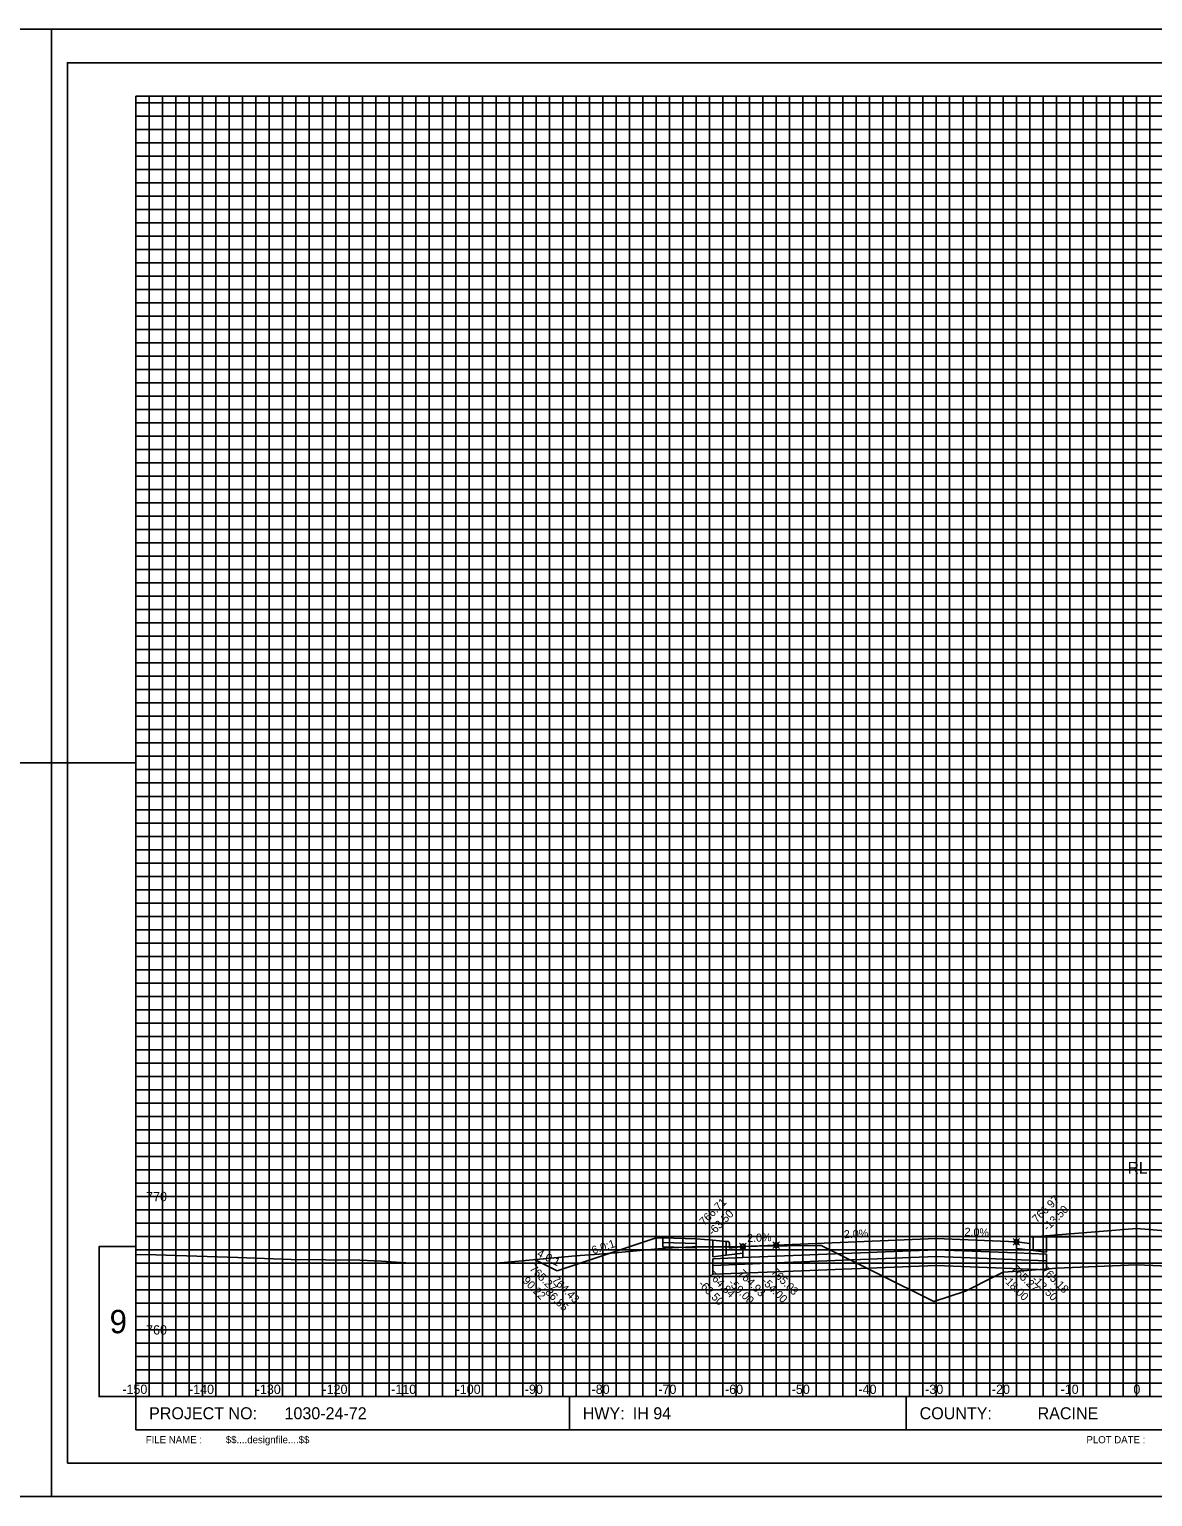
# Model space of a CAD drawing. Extents: x 578243 to 601557, y 174899 to 175559.
# Drawn here: x 601213.9 to 601382.3, y 174898.8 to 175118.8 of the extents above; entities that cross this region are included whole.
import ezdxf

# ---------------------------------------------------------------- set-up
doc = ezdxf.new("R2010")
doc.units = 0
for name, color, linetype in [('E_PROF_Grid', 7, 'Continuous'), ('E_PROF_GridMin', 7, 'Continuous'), ('P_CRDR_Label', 7, 'Continuous'), ('P_CRDR_Link', 7, 'Continuous'), ('P_E_XS_Ground', 7, 'Continuous'), ('P_XS_Text', 7, 'Continuous'), ('PLT_Sheet_Border', 7, 'Continuous'), ('PLT_Sheet_Info', 7, 'Continuous')]:
    doc.layers.add(name, color=color, linetype=linetype)

msp = doc.modelspace()

# ---------------------------------------------------------------- linework, layer by layer
at = {"layer": 'E_PROF_Grid'}
for p, q in [((601239.84, 174913.8), (601239.84, 175108.8)), ((601249.84, 174913.8), (601249.84, 175108.8)), ((601259.84, 174913.8), (601259.84, 175108.8)), ((601269.84, 174913.8), (601269.84, 175108.8)), ((601279.84, 174913.8), (601279.84, 175108.8)), ((601289.84, 174913.8), (601289.84, 175108.8)), ((601299.84, 174913.8), (601299.84, 175108.8)), ((601309.84, 174913.8), (601309.84, 175108.8)), ((601319.84, 174913.8), (601319.84, 175108.8)), ((601329.84, 174913.8), (601329.84, 175108.8)), ((601339.84, 174913.8), (601339.84, 175108.8)), ((601349.84, 174913.8), (601349.84, 175108.8)), ((601359.84, 174913.8), (601359.84, 175108.8)), ((601369.84, 174913.8), (601369.84, 175108.8)), ((601379.84, 174913.8), (601379.84, 175108.8)), ((601229.84, 175103.8), (601544.84, 175103.8)), ((601229.84, 175093.8), (601544.84, 175093.8)), ((601229.84, 175083.8), (601544.84, 175083.8)), ((601229.84, 175073.8), (601544.84, 175073.8)), ((601229.84, 175063.8), (601544.84, 175063.8)), ((601229.84, 175053.8), (601544.84, 175053.8)), ((601229.84, 175043.8), (601544.84, 175043.8)), ((601229.84, 175033.8), (601544.84, 175033.8)), ((601229.84, 175023.8), (601544.84, 175023.8)), ((601229.84, 175013.8), (601544.84, 175013.8)), ((601229.84, 175003.8), (601544.84, 175003.8)), ((601229.84, 174993.8), (601544.84, 174993.8)), ((601229.84, 174983.8), (601544.84, 174983.8)), ((601229.84, 174973.8), (601544.84, 174973.8)), ((601229.84, 174963.8), (601544.84, 174963.8)), ((601229.84, 174953.8), (601544.84, 174953.8)), ((601229.84, 174943.8), (601544.84, 174943.8)), ((601229.84, 174933.8), (601544.84, 174933.8)), ((601229.84, 174923.8), (601544.84, 174923.8))]:
    msp.add_line(p, q, dxfattribs=at)
at = {"layer": 'E_PROF_GridMin'}
for p, q in [((601229.84, 175107.8), (601544.84, 175107.8)), ((601231.84, 174913.8), (601231.84, 175108.8)), ((601233.84, 174913.8), (601233.84, 175108.8)), ((601235.84, 174913.8), (601235.84, 175108.8)), ((601237.84, 174913.8), (601237.84, 175108.8)), ((601241.84, 174913.8), (601241.84, 175108.8)), ((601243.84, 174913.8), (601243.84, 175108.8)), ((601245.84, 174913.8), (601245.84, 175108.8)), ((601247.84, 174913.8), (601247.84, 175108.8)), ((601251.84, 174913.8), (601251.84, 175108.8)), ((601253.84, 174913.8), (601253.84, 175108.8)), ((601255.84, 174913.8), (601255.84, 175108.8)), ((601257.84, 174913.8), (601257.84, 175108.8)), ((601261.84, 174913.8), (601261.84, 175108.8)), ((601263.84, 174913.8), (601263.84, 175108.8)), ((601265.84, 174913.8), (601265.84, 175108.8)), ((601267.84, 174913.8), (601267.84, 175108.8)), ((601271.84, 174913.8), (601271.84, 175108.8)), ((601273.84, 174913.8), (601273.84, 175108.8)), ((601275.84, 174913.8), (601275.84, 175108.8)), ((601277.84, 174913.8), (601277.84, 175108.8)), ((601281.84, 174913.8), (601281.84, 175108.8)), ((601283.84, 174913.8), (601283.84, 175108.8)), ((601285.84, 174913.8), (601285.84, 175108.8)), ((601287.84, 174913.8), (601287.84, 175108.8)), ((601291.84, 174913.8), (601291.84, 175108.8)), ((601293.84, 174913.8), (601293.84, 175108.8)), ((601295.84, 174913.8), (601295.84, 175108.8)), ((601297.84, 174913.8), (601297.84, 175108.8)), ((601301.84, 174913.8), (601301.84, 175108.8)), ((601303.84, 174913.8), (601303.84, 175108.8)), ((601305.84, 174913.8), (601305.84, 175108.8)), ((601307.84, 174913.8), (601307.84, 175108.8)), ((601311.84, 174913.8), (601311.84, 175108.8)), ((601313.84, 174913.8), (601313.84, 175108.8)), ((601315.84, 174913.8), (601315.84, 175108.8)), ((601317.84, 174913.8), (601317.84, 175108.8)), ((601321.84, 174913.8), (601321.84, 175108.8)), ((601323.84, 174913.8), (601323.84, 175108.8)), ((601325.84, 174913.8), (601325.84, 175108.8)), ((601327.84, 174913.8), (601327.84, 175108.8)), ((601331.84, 174913.8), (601331.84, 175108.8)), ((601333.84, 174913.8), (601333.84, 175108.8)), ((601335.84, 174913.8), (601335.84, 175108.8)), ((601337.84, 174913.8), (601337.84, 175108.8)), ((601341.84, 174913.8), (601341.84, 175108.8)), ((601343.84, 174913.8), (601343.84, 175108.8)), ((601345.84, 174913.8), (601345.84, 175108.8)), ((601347.84, 174913.8), (601347.84, 175108.8)), ((601351.84, 174913.8), (601351.84, 175108.8)), ((601353.84, 174913.8), (601353.84, 175108.8)), ((601355.84, 174913.8), (601355.84, 175108.8)), ((601357.84, 174913.8), (601357.84, 175108.8)), ((601361.84, 174913.8), (601361.84, 175108.8)), ((601363.84, 174913.8), (601363.84, 175108.8)), ((601365.84, 174913.8), (601365.84, 175108.8)), ((601367.84, 174913.8), (601367.84, 175108.8)), ((601371.84, 174913.8), (601371.84, 175108.8)), ((601373.84, 174913.8), (601373.84, 175108.8)), ((601375.84, 174913.8), (601375.84, 175108.8)), ((601377.84, 174913.8), (601377.84, 175108.8)), ((601381.84, 174913.8), (601381.84, 175108.8)), ((601229.84, 175105.8), (601544.84, 175105.8)), ((601229.84, 175101.8), (601544.84, 175101.8)), ((601229.84, 175099.8), (601544.84, 175099.8)), ((601229.84, 175097.8), (601544.84, 175097.8)), ((601229.84, 175095.8), (601544.84, 175095.8)), ((601229.84, 175091.8), (601544.84, 175091.8)), ((601229.84, 175089.8), (601544.84, 175089.8)), ((601229.84, 175087.8), (601544.84, 175087.8)), ((601229.84, 175085.8), (601544.84, 175085.8)), ((601229.84, 175081.8), (601544.84, 175081.8)), ((601229.84, 175079.8), (601544.84, 175079.8)), ((601229.84, 175077.8), (601544.84, 175077.8)), ((601229.84, 175075.8), (601544.84, 175075.8)), ((601229.84, 175071.8), (601544.84, 175071.8)), ((601229.84, 175069.8), (601544.84, 175069.8)), ((601229.84, 175067.8), (601544.84, 175067.8)), ((601229.84, 175065.8), (601544.84, 175065.8)), ((601229.84, 175061.8), (601544.84, 175061.8)), ((601229.84, 175059.8), (601544.84, 175059.8)), ((601229.84, 175057.8), (601544.84, 175057.8)), ((601229.84, 175055.8), (601544.84, 175055.8)), ((601229.84, 175051.8), (601544.84, 175051.8)), ((601229.84, 175049.8), (601544.84, 175049.8)), ((601229.84, 175047.8), (601544.84, 175047.8)), ((601229.84, 175045.8), (601544.84, 175045.8)), ((601229.84, 175041.8), (601544.84, 175041.8)), ((601229.84, 175039.8), (601544.84, 175039.8)), ((601229.84, 175037.8), (601544.84, 175037.8)), ((601229.84, 175035.8), (601544.84, 175035.8)), ((601229.84, 175031.8), (601544.84, 175031.8)), ((601229.84, 175029.8), (601544.84, 175029.8)), ((601229.84, 175027.8), (601544.84, 175027.8)), ((601229.84, 175025.8), (601544.84, 175025.8)), ((601229.84, 175021.8), (601544.84, 175021.8)), ((601229.84, 175019.8), (601544.84, 175019.8)), ((601229.84, 175017.8), (601544.84, 175017.8)), ((601229.84, 175015.8), (601544.84, 175015.8)), ((601229.84, 175011.8), (601544.84, 175011.8)), ((601229.84, 175009.8), (601544.84, 175009.8)), ((601229.84, 175007.8), (601544.84, 175007.8)), ((601229.84, 175005.8), (601544.84, 175005.8)), ((601229.84, 175001.8), (601544.84, 175001.8)), ((601229.84, 174999.8), (601544.84, 174999.8)), ((601229.84, 174997.8), (601544.84, 174997.8)), ((601229.84, 174995.8), (601544.84, 174995.8)), ((601229.84, 174991.8), (601544.84, 174991.8)), ((601229.84, 174989.8), (601544.84, 174989.8)), ((601229.84, 174987.8), (601544.84, 174987.8)), ((601229.84, 174985.8), (601544.84, 174985.8)), ((601229.84, 174981.8), (601544.84, 174981.8)), ((601229.84, 174979.8), (601544.84, 174979.8)), ((601229.84, 174977.8), (601544.84, 174977.8)), ((601229.84, 174975.8), (601544.84, 174975.8)), ((601229.84, 174971.8), (601544.84, 174971.8)), ((601229.84, 174969.8), (601544.84, 174969.8)), ((601229.84, 174967.8), (601544.84, 174967.8)), ((601229.84, 174965.8), (601544.84, 174965.8)), ((601229.84, 174961.8), (601544.84, 174961.8)), ((601229.84, 174959.8), (601544.84, 174959.8)), ((601229.84, 174957.8), (601544.84, 174957.8)), ((601229.84, 174955.8), (601544.84, 174955.8)), ((601229.84, 174951.8), (601544.84, 174951.8)), ((601229.84, 174949.8), (601544.84, 174949.8)), ((601229.84, 174947.8), (601544.84, 174947.8)), ((601229.84, 174945.8), (601544.84, 174945.8)), ((601229.84, 174941.8), (601544.84, 174941.8)), ((601229.84, 174939.8), (601544.84, 174939.8)), ((601229.84, 174937.8), (601544.84, 174937.8)), ((601229.84, 174935.8), (601544.84, 174935.8)), ((601229.84, 174931.8), (601544.84, 174931.8)), ((601229.84, 174929.8), (601544.84, 174929.8)), ((601229.84, 174927.8), (601544.84, 174927.8)), ((601229.84, 174925.8), (601544.84, 174925.8)), ((601229.84, 174921.8), (601544.84, 174921.8)), ((601229.84, 174919.8), (601544.84, 174919.8)), ((601229.84, 174917.8), (601544.84, 174917.8)), ((601229.84, 174915.8), (601544.84, 174915.8)), ((601217.19, 174898.8), (601217.19, 174908.8)), ((601207.19, 174898.8), (601217.19, 174898.8))]:
    msp.add_line(p, q, dxfattribs=at)
at = {"layer": 'P_CRDR_Label'}
for points in [[(601379.84, 174946.61), (601379.84, 174938.99)], [(601361.34, 174936.5), (601362.33, 174937.49)], [(601361.34, 174937.49), (601362.33, 174936.5)], [(601320.34, 174935.82), (601321.33, 174936.81)], [(601320.34, 174936.81), (601321.33, 174935.82)], [(601325.34, 174936.02), (601326.33, 174937.01)], [(601325.34, 174937.01), (601326.33, 174936.02)]]:
    msp.add_lwpolyline(points, dxfattribs=at)
for centre in [(601320.84, 174936.32), (601325.84, 174936.52), (601361.84, 174937)]:
    msp.add_circle(centre, 0.35, dxfattribs=at)
at = {"layer": 'P_CRDR_Link'}
for points in [[(601307.84, 174937.61), (601292.99, 174932.66)], [(601307.84, 174937.61), (601292.99, 174932.66)], [(601308.84, 174937.58), (601307.84, 174937.61)], [(601308.84, 174937.58), (601307.84, 174937.61)], [(601313.84, 174937.43), (601308.84, 174937.58)], [(601313.84, 174937.43), (601308.84, 174937.58)], [(601308.84, 174937.58), (601308.84, 174936.91)], [(601313.84, 174937.43), (601313.83, 174936.76)], [(601316.34, 174937.23), (601313.84, 174937.43)], [(601316.34, 174937.23), (601313.84, 174937.43)], [(601349.84, 174937.48), (601325.84, 174936.52)], [(601361.84, 174937), (601349.84, 174937.48)], [(601349.84, 174937.48), (601349.84, 174935.81)], [(601349.84, 174937.48), (601349.84, 174935.81)], [(601363.84, 174936.75), (601363.85, 174937.43)], [(601363.84, 174936.75), (601363.85, 174937.43)], [(601363.85, 174937.43), (601363.88, 174937.59)], [(601363.85, 174937.43), (601363.88, 174937.59)], [(601363.88, 174937.59), (601363.94, 174937.7)], [(601363.88, 174937.59), (601363.94, 174937.7)], [(601363.94, 174937.7), (601364.02, 174937.75)], [(601363.94, 174937.7), (601364.02, 174937.75)], [(601364.02, 174937.75), (601364.34, 174937.75)], [(601364.02, 174937.75), (601364.34, 174937.75)], [(601364.34, 174937.75), (601379.84, 174938.99)], [(601364.34, 174937.75), (601379.84, 174938.99)], [(601364.34, 174937.75), (601364.34, 174935.68)], [(601364.34, 174937.75), (601366.34, 174937.73)], [(601364.34, 174935.68), (601364.34, 174937.75)], [(601366.34, 174937.73), (601366.34, 174935.43)], [(601366.34, 174937.73), (601366.34, 174935.43)], [(601366.34, 174937.73), (601366.34, 174935.43)], [(601366.34, 174937.73), (601369.84, 174937.7)], [(601366.34, 174937.73), (601369.84, 174937.7)], [(601395.34, 174937.75), (601379.84, 174938.99)], [(601395.34, 174937.75), (601379.84, 174938.99)], [(601313.83, 174936.76), (601308.84, 174936.91)], [(601308.85, 174936.25), (601308.84, 174936.91)], [(601313.83, 174936.1), (601308.85, 174936.25)], [(601313.83, 174936.76), (601313.83, 174936.1)], [(601318.34, 174937.07), (601316.34, 174937.23)], [(601316.34, 174937.23), (601316.34, 174934.75)], [(601316.34, 174937.23), (601316.34, 174934.75)], [(601316.34, 174937.23), (601316.34, 174934.75)], [(601318.66, 174937.07), (601318.34, 174937.07)], [(601318.66, 174937.07), (601318.34, 174937.07)], [(601318.34, 174937.07), (601318.34, 174935)], [(601318.34, 174935), (601318.34, 174937.07)], [(601318.34, 174935), (601320.84, 174935.32)], [(601318.34, 174935), (601320.84, 174935.32)], [(601318.74, 174937.02), (601318.66, 174937.07)], [(601318.74, 174937.02), (601318.66, 174937.07)], [(601318.8, 174936.91), (601318.74, 174937.02)], [(601318.8, 174936.91), (601318.74, 174937.02)], [(601318.82, 174936.75), (601318.8, 174936.91)], [(601318.82, 174936.75), (601318.8, 174936.91)], [(601318.84, 174936.07), (601318.82, 174936.75)], [(601318.84, 174936.07), (601318.82, 174936.75)], [(601320.84, 174936.32), (601318.84, 174936.07)], [(601320.84, 174936.32), (601318.84, 174936.07)], [(601325.84, 174936.52), (601320.84, 174936.32)], [(601320.84, 174936.32), (601320.84, 174934.65)], [(601320.84, 174935.32), (601320.84, 174936.32)], [(601325.84, 174936.52), (601325.84, 174934.85)], [(601325.84, 174936.52), (601325.84, 174934.85)], [(601349.84, 174935.81), (601325.84, 174934.85)], [(601361.84, 174935.33), (601349.84, 174935.81)], [(601349.84, 174935.81), (601349.84, 174934.81)], [(601349.84, 174935.81), (601349.84, 174934.81)], [(601361.84, 174937), (601363.84, 174936.75)], [(601361.84, 174937), (601363.84, 174936.75)], [(601361.84, 174936), (601361.84, 174937)], [(601361.84, 174937), (601361.84, 174935.33)], [(601364.34, 174935.68), (601361.84, 174936)], [(601364.34, 174935.68), (601361.84, 174936)], [(601366.34, 174935.15), (601361.84, 174935.33)], [(601366.34, 174935.43), (601364.34, 174935.68)], [(601292.99, 174932.66), (601289.62, 174934.34)], [(601292.99, 174932.66), (601289.62, 174934.34)], [(601316.34, 174934.75), (601318.34, 174935)], [(601320.84, 174934.65), (601316.34, 174934.47)], [(601316.34, 174934.47), (601316.34, 174933.47)], [(601325.84, 174933.85), (601316.34, 174933.47)], [(601316.34, 174933.47), (601316.34, 174932.14)], [(601325.84, 174934.85), (601320.84, 174934.65)], [(601325.84, 174934.85), (601325.84, 174933.85)], [(601325.84, 174934.85), (601325.84, 174933.85)], [(601349.84, 174934.81), (601325.84, 174933.85)], [(601325.84, 174933.85), (601325.84, 174932.52)], [(601325.84, 174933.85), (601325.84, 174932.52)], [(601349.84, 174933.48), (601325.84, 174932.52)], [(601366.34, 174934.15), (601349.84, 174934.81)], [(601349.84, 174934.81), (601349.84, 174933.48)], [(601349.84, 174934.81), (601349.84, 174933.48)], [(601366.34, 174932.82), (601349.84, 174933.48)], [(601366.34, 174935.15), (601366.34, 174934.15)], [(601366.34, 174934.15), (601366.34, 174932.82)], [(601325.84, 174932.52), (601316.34, 174932.14)]]:
    msp.add_lwpolyline(points, dxfattribs=at)
at = {"layer": 'P_E_XS_Ground'}
msp.add_lwpolyline([(601229.84, 174935.12), (601232.85, 174935.04), (601245.13, 174934.64), (601253.13, 174934.37), (601263.45, 174934.27), (601266.66, 174934.11), (601270.34, 174933.88), (601275.98, 174933.81), (601278.64, 174933.8), (601283.46, 174933.8), (601283.74, 174933.79), (601285.07, 174933.91), (601295.75, 174934.92), (601300.02, 174935.2), (601309.24, 174936.03), (601313.3, 174936.25), (601319.18, 174936.25), (601323.02, 174936.34), (601327.46, 174936.39), (601331.89, 174936.47), (601332.58, 174936.47), (601349.45, 174928.04), (601354.2, 174929.62), (601358.54, 174931.79), (601359.84, 174932.44), (601362.84, 174932.68), (601367.84, 174933.08), (601379.84, 174933.56), (601396.84, 174932.88)], dxfattribs=at)
at = {"layer": 'PLT_Sheet_Border'}
for points in [[(600877.19, 174898.8), (601217.19, 174898.8), (601217.19, 175118.8), (600877.19, 175118.8)], [(601217.19, 174898.8), (601557.19, 174898.8), (601557.19, 175118.8), (601217.19, 175118.8)], [(601219.59, 174903.8), (601550.59, 174903.8), (601550.59, 175113.8), (601219.59, 175113.8)]]:
    msp.add_lwpolyline(points, close=True, dxfattribs=at)
at = {"layer": 'PLT_Sheet_Info'}
for p, q in [((601207.19, 175118.8), (601217.19, 175118.8)), ((601217.19, 175108.8), (601217.19, 175118.8)), ((601217.19, 175108.8), (601217.19, 175118.8)), ((601217.19, 175118.8), (601227.19, 175118.8)), ((601229.84, 175108.8), (601544.84, 175108.8)), ((601229.84, 174908.8), (601229.84, 175108.8)), ((601217.19, 175003.8), (601217.19, 175013.8)), ((601217.19, 175003.8), (601217.19, 175013.8)), ((601217.19, 175008.8), (601204.84, 175008.8)), ((601217.19, 175008.8), (601229.84, 175008.8)), ((601229.84, 174913.8), (601544.84, 174913.8)), ((601294.84, 174908.8), (601294.84, 174913.8)), ((601345.34, 174908.8), (601345.34, 174913.8)), ((601217.19, 174898.8), (601217.19, 174908.8)), ((601229.84, 174908.8), (601544.84, 174908.8)), ((601217.19, 174898.8), (601227.19, 174898.8))]:
    msp.add_line(p, q, dxfattribs=at)
msp.add_lwpolyline([(601229.84, 174936.3), (601224.34, 174936.3), (601224.34, 174913.8), (601229.84, 174913.8)], close=True, dxfattribs=at)

# ---------------------------------------------------------------- texts
at = {"layer": 'P_CRDR_Label'}
msp.add_text('RL', height=1.75, dxfattribs=at).set_placement((601378.51, 174947.24))
for s, rotation, p in [('766.97', 45, (601364.92, 174939.77)), ('766.71', 45, (601315.03, 174939.38)), ('-13.50', 45, (601366.52, 174938.54)), ('-63.50', 45, (601316.34, 174937.86)), ('2.0%', 2.2906, (601321.5, 174936.96)), ('2.0%', 2.2906, (601336, 174937.54)), ('2.0%', 357.7094, (601354.05, 174937.93)), ('4.0:1', 333.4349, (601289.88, 174934.9)), ('6.0:1', 18.4349, (601298.42, 174935.12)), ('765.27', 315, (601288.77, 174932.86)), ('765.27', 315, (601288.77, 174932.86)), ('765.03', 315, (601324.99, 174932.37)), ('765.27', 315, (601360.99, 174932.85)), ('765.18', 315, (601365.49, 174932.67)), ('-90.22', 315, (601287.36, 174931.45)), ('-90.22', 315, (601287.36, 174931.45)), ('764.43', 315, (601292.14, 174931.18)), ('-63.50', 315, (601314.08, 174930.58)), ('764.84', 315, (601315.49, 174931.99)), ('-59.00', 315, (601318.58, 174930.76)), ('764.93', 315, (601320.02, 174932.14)), ('-54.00', 315, (601323.58, 174930.96)), ('-18.00', 315, (601359.73, 174931.29)), ('-13.50', 315, (601364.08, 174931.26)), ('-86.85', 315, (601290.76, 174929.73))]:
    msp.add_text(s, height=1.2, rotation=rotation, dxfattribs=at).set_placement(p)
at = {"layer": 'P_XS_Text'}
for s, p in [('770', (601231.4, 174943.1)), ('760', (601231.4, 174923.1)), ('-150', (601227.83, 174914.2)), ('-140', (601237.83, 174914.2)), ('-130', (601247.83, 174914.2)), ('-120', (601257.83, 174914.2)), ('-110', (601268.13, 174914.2)), ('-100', (601277.79, 174914.2)), ('-90', (601288.16, 174914.2)), ('-80', (601298.17, 174914.2)), ('-70', (601308.17, 174914.2)), ('-60', (601318.17, 174914.2)), ('-50', (601328.17, 174914.2)), ('-40', (601338.17, 174914.2)), ('-30', (601348.17, 174914.2)), ('-20', (601358.17, 174914.2)), ('-10', (601368.47, 174914.2)), ('0', (601379.38, 174914.2)), ('0', (601379.38, 174914.2))]:
    msp.add_text(s, height=1.4, rotation=360, dxfattribs=at).set_placement(p)
at = {"layer": 'PLT_Sheet_Info'}
for s, height, p in [('9', 3.5, (601225.92, 174923.3)), ('PROJECT NO:', 1.8, (601231.84, 174910.4)), ('1030-24-72             ', 1.8, (601252.14, 174910.4)), ('HWY:', 1.8, (601296.84, 174910.4)), ('IH 94               ', 1.8, (601304.34, 174910.4)), ('COUNTY:', 1.8, (601347.34, 174910.4)), ('       RACINE       ', 1.8, (601360.34, 174910.4)), ('FILE NAME :', 1.08, (601231.34, 174906.8))]:
    msp.add_text(s, height=height, dxfattribs=at).set_placement(p)
for s, p in [('$$....designfile....$$', (601243.34, 174906.8)), ('PLOT DATE :', (601372.34, 174906.8))]:
    msp.add_text(s, height=1.08, rotation=360, dxfattribs=at).set_placement(p)

doc.saveas('drawing.dxf')
